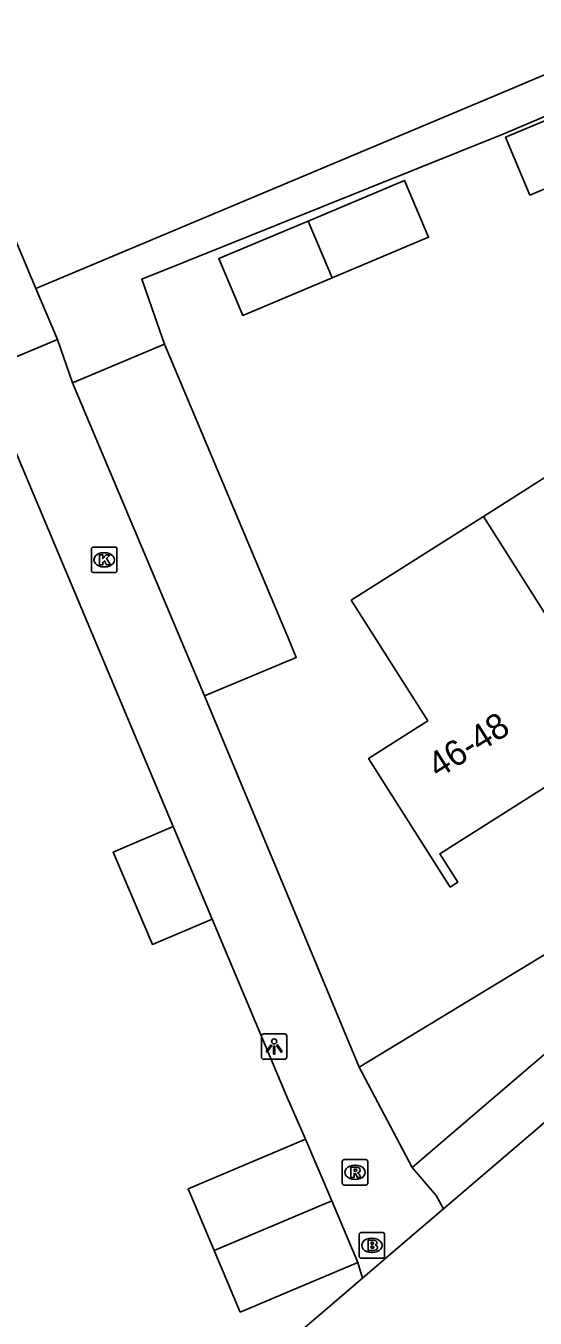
# Model space of a CAD drawing. Extents: x 157767 to 159171, y 387842 to 389425.
# Drawn here: x 158989.6 to 159009.6, y 388129.2 to 388179.9 of the extents above; entities that cross this region are included whole.
import ezdxf

# ---------------------------------------------------------------- set-up
doc = ezdxf.new("R2010")
doc.units = 0
for name, color, linetype in [('IMGEO_Brandkraan', 7, 'Continuous'), ('IMGEO_Fietspad_gesloten', 7, 'Continuous'), ('IMGEO_Kolk', 7, 'Continuous'), ('IMGEO_Lichtpunt', 7, 'Continuous'), ('IMGEO_Pand', 7, 'Continuous'), ('IMGEO_Pand_nummerreeks', 7, 'Continuous'), ('IMGEO_Rioolput', 7, 'Continuous'), ('IMGEO_Voetpad_open', 7, 'Continuous')]:
    doc.layers.add(name, color=color, linetype=linetype)

msp = doc.modelspace()

# ---------------------------------------------------------------- linework, layer by layer
at = {"layer": 'IMGEO_Brandkraan'}
for p, q in [((159002.719, 388131.627), (159002.719, 388132.479)), ((159002.794, 388132.553), (159003.646, 388132.553)), ((159003.207, 388132.333), (159003.232, 388132.333)), ((159003.72, 388132.479), (159003.72, 388131.627)), ((159003.23, 388131.773), (159003.205, 388131.773)), ((159003.646, 388131.553), (159002.794, 388131.553))]:
    msp.add_line(p, q, dxfattribs=at)
for points in [[(159002.719, 388131.627), (159002.719, 388132.479)], [(159002.794, 388132.553), (159003.646, 388132.553)], [(159003.72, 388132.479), (159003.72, 388131.627)], [(159003.067, 388132.253), (159003.067, 388131.853), (159003.28, 388131.853)], [(159003.298, 388132.253), (159003.067, 388132.253)], [(159003.246, 388132.172), (159003.192, 388132.172), (159003.192, 388132.096)], [(159003.192, 388132.096), (159003.245, 388132.096)], [(159003.254, 388132.02), (159003.192, 388132.02), (159003.192, 388131.939)], [(159003.192, 388131.939), (159003.254, 388131.939)], [(159003.646, 388131.553), (159002.794, 388131.553)]]:
    msp.add_lwpolyline(points, dxfattribs=at)
for centre, radius, start, end in [((159002.796, 388132.477), 0.0765, 91.552, 178.448), ((159002.796, 388132.477), 0.0765, 91.552, 178.448), ((159003.644, 388132.477), 0.0765, 1.552, 88.448), ((159003.644, 388132.477), 0.0765, 1.552, 88.448), ((159003.247, 388132.134), 0.0379, 267.8285, 90.9355), ((159003.255, 388131.979), 0.0404, 269.8759, 90.5077), ((159003.286, 388132.104), 0.251, 268.6676, 293.5347), ((159003.302, 388132.108), 0.145, 59.4692, 91.5367), ((159003.327, 388132.155), 0.0922, 285.5137, 58.1501), ((159003.332, 388131.963), 0.105, 301.3115, 78.989), ((159002.796, 388131.629), 0.0765, 181.552, 268.448), ((159002.796, 388131.629), 0.0765, 181.552, 268.448), ((159003.644, 388131.629), 0.0765, 271.552, 358.448), ((159003.644, 388131.629), 0.0765, 271.552, 358.448)]:
    msp.add_arc(centre, radius, start, end, dxfattribs=at)
for centre, major_axis, ratio, start_param, end_param in [((159003.206, 388132.053), (-0.387, 0.002), 0.722429, 4.712389, 7.853982), ((159003.231, 388132.053), (-0.39, 0.002), 0.717154, 1.570796, 4.712389)]:
    msp.add_ellipse(centre, major_axis=major_axis, ratio=ratio, start_param=start_param, end_param=end_param, dxfattribs=at)
at = {"layer": 'IMGEO_Fietspad_gesloten'}
for points in [[(159053.249, 388168.568), (159030.332, 388154.206), (159025.936, 388150.51), (159006.031, 388133.49)], [(159006.031, 388133.49), (159004.522, 388132.2), (159002.853, 388130.771)], [(159002.853, 388130.771), (158986.676, 388116.918), (158982.857, 388113.648)]]:
    msp.add_lwpolyline(points, dxfattribs=at)
at = {"layer": 'IMGEO_Kolk'}
for p, q in [((158992.214, 388158.538), (158992.214, 388159.39)), ((158992.289, 388159.464), (158993.141, 388159.464)), ((158992.702, 388159.244), (158992.727, 388159.244)), ((158993.215, 388159.39), (158993.215, 388158.538)), ((158992.725, 388158.684), (158992.7, 388158.684)), ((158993.141, 388158.464), (158992.289, 388158.464))]:
    msp.add_line(p, q, dxfattribs=at)
for points in [[(158992.214, 388158.538), (158992.214, 388159.39)], [(158992.289, 388159.464), (158993.141, 388159.464)], [(158992.535, 388159.164), (158992.658, 388159.164), (158992.658, 388159.013), (158992.788, 388159.164), (158992.952, 388159.164), (158992.806, 388159.013), (158992.959, 388158.764), (158992.807, 388158.764), (158992.722, 388158.928), (158992.658, 388158.861), (158992.658, 388158.764), (158992.535, 388158.764), (158992.535, 388159.164)], [(158993.215, 388159.39), (158993.215, 388158.538)], [(158993.141, 388158.464), (158992.289, 388158.464)]]:
    msp.add_lwpolyline(points, dxfattribs=at)
for centre, start, end in [((158992.291, 388159.388), 91.552, 178.448), ((158992.291, 388159.388), 91.552, 178.448), ((158993.139, 388159.388), 1.552, 88.448), ((158993.139, 388159.388), 1.552, 88.448), ((158992.291, 388158.54), 181.552, 268.448), ((158992.291, 388158.54), 181.552, 268.448), ((158993.139, 388158.54), 271.552, 358.448), ((158993.139, 388158.54), 271.552, 358.448)]:
    msp.add_arc(centre, 0.0765, start, end, dxfattribs=at)
for centre, major_axis, ratio, start_param, end_param in [((158992.701, 388158.964), (-0.387, 0.002), 0.722429, 4.712389, 7.853982), ((158992.726, 388158.964), (-0.39, 0.002), 0.717154, 1.570796, 4.712389)]:
    msp.add_ellipse(centre, major_axis=major_axis, ratio=ratio, start_param=start_param, end_param=end_param, dxfattribs=at)
at = {"layer": 'IMGEO_Lichtpunt'}
for p, q in [((158998.885, 388140.262), (158998.885, 388139.455)), ((158998.885, 388140.262), (158998.885, 388139.455)), ((158999.787, 388140.357), (158998.979, 388140.357)), ((158999.787, 388140.357), (158998.979, 388140.357)), ((158999.881, 388139.455), (158999.881, 388140.262)), ((158999.881, 388139.455), (158999.881, 388140.262)), ((158998.979, 388139.361), (158999.787, 388139.361)), ((158998.979, 388139.361), (158999.787, 388139.361))]:
    msp.add_line(p, q, dxfattribs=at)
for points in [[(158999.259, 388139.926), (158999.298, 388139.898), (158999.11, 388139.636), (158999.072, 388139.663), (158999.259, 388139.926)], [(158999.471, 388139.898), (158999.509, 388139.925), (158999.696, 388139.663), (158999.657, 388139.635), (158999.471, 388139.898)], [(158999.361, 388139.878), (158999.408, 388139.878), (158999.408, 388139.556), (158999.361, 388139.556), (158999.361, 388139.878)]]:
    msp.add_lwpolyline(points, dxfattribs=at)
msp.add_circle((158999.384, 388140.06), 0.0994, dxfattribs=at)
for centre, start, end in [((158998.979, 388140.262), 90, 180), ((158998.979, 388140.262), 90, 180), ((158999.787, 388140.262), 0, 90), ((158999.787, 388140.262), 0, 90), ((158998.979, 388139.455), 180, 270), ((158998.979, 388139.455), 180, 270), ((158999.787, 388139.455), 270, 0), ((158999.787, 388139.455), 270, 360)]:
    msp.add_arc(centre, 0.0946, start, end, dxfattribs=at)
at = {"layer": 'IMGEO_Pand'}
for points in [[(159012.093, 388177.078), (159008.463, 388175.549), (159009.418, 388173.282), (159013.048, 388174.811)], [(159001.655, 388170.032), (159005.444, 388171.628), (159004.504, 388173.858), (159000.716, 388172.262)], [(159000.716, 388172.262), (159000.341, 388172.105), (158997.211, 388170.786), (158998.151, 388168.556), (159001.655, 388170.032)], [(159001.655, 388170.032), (159000.716, 388172.262)], [(158987.408, 388170.892), (158989.185, 388171.639), (158990.035, 388169.616)], [(158990.035, 388169.616), (158990.878, 388167.608)], [(158990.878, 388167.608), (158989.104, 388166.863)], [(158991.474, 388165.913), (158995.076, 388167.43)], [(158995.076, 388167.43), (159000, 388155.739), (159000.254, 388155.135), (159000, 388155.028), (158996.653, 388153.618)], [(158996.653, 388153.618), (158991.474, 388165.913)], [(159007.593, 388160.666), (159012.68, 388163.891)], [(159013.094, 388151.989), (159005.882, 388147.416), (159006.587, 388146.305), (159006.293, 388146.118), (159003.092, 388151.167), (159005.411, 388152.637), (159002.406, 388157.377), (159007.593, 388160.666)], [(159007.593, 388160.666), (159013.094, 388151.989)], [(158996.953, 388144.862), (158994.605, 388143.866), (158993.067, 388147.494), (158995.415, 388148.489)], [(158995.415, 388148.489), (158996.953, 388144.862)], [(158997.033, 388131.851), (158996.011, 388134.27), (159000, 388135.956), (159000.62, 388136.217)], [(159000.62, 388136.217), (159001.644, 388133.794)], [(159001.644, 388133.794), (158997.033, 388131.851)], [(159001.644, 388133.794), (159002.664, 388131.38)], [(159002.664, 388131.38), (159000, 388130.255), (158998.055, 388129.433), (158997.033, 388131.851)]]:
    msp.add_lwpolyline(points, dxfattribs=at)
at = {"layer": 'IMGEO_Rioolput'}
for p, q in [((159002.058, 388134.495), (159002.058, 388135.347)), ((159002.133, 388135.421), (159002.985, 388135.421)), ((159003.059, 388135.347), (159003.059, 388134.495)), ((159002.546, 388135.201), (159002.571, 388135.201)), ((159002.985, 388134.421), (159002.133, 388134.421)), ((159002.569, 388134.641), (159002.544, 388134.641))]:
    msp.add_line(p, q, dxfattribs=at)
for points in [[(159002.058, 388134.495), (159002.058, 388135.347)], [(159002.133, 388135.421), (159002.985, 388135.421)], [(159003.059, 388135.347), (159003.059, 388134.495)], [(159002.647, 388135.119), (159002.395, 388135.121), (159002.395, 388134.721)], [(159002.395, 388134.721), (159002.519, 388134.721), (159002.519, 388134.883), (159002.53, 388134.883)], [(159002.573, 388135.04), (159002.519, 388135.04), (159002.519, 388134.959)], [(159002.519, 388134.959), (159002.571, 388134.959)], [(159002.577, 388134.854), (159002.648, 388134.721), (159002.788, 388134.721), (159002.723, 388134.847)], [(159002.985, 388134.421), (159002.133, 388134.421)]]:
    msp.add_lwpolyline(points, dxfattribs=at)
for centre, radius, start, end in [((159002.135, 388135.345), 0.0765, 91.552, 178.448), ((159002.135, 388135.345), 0.0765, 91.552, 178.448), ((159002.983, 388135.345), 0.0765, 1.552, 88.448), ((159002.983, 388135.345), 0.0765, 1.552, 88.448), ((159002.529, 388134.83), 0.0533, 26.0293, 88.6989), ((159002.555, 388135.148), 0.19, 274.7715, 282.9687), ((159002.579, 388134.944), 0.0964, 77.0061, 93.1865), ((159002.593, 388135.001), 0.0378, 276.6634, 79.6772), ((159002.646, 388135.009), 0.109, 350.3612, 89.416), ((159002.644, 388135.009), 0.112, 277.5842, 350.9817), ((159002.628, 388134.794), 0.108, 29.5134, 73.7905), ((159002.135, 388134.497), 0.0765, 181.552, 268.448), ((159002.135, 388134.497), 0.0765, 181.552, 268.448), ((159002.983, 388134.497), 0.0765, 271.552, 358.448), ((159002.983, 388134.497), 0.0765, 271.552, 358.448)]:
    msp.add_arc(centre, radius, start, end, dxfattribs=at)
for centre, major_axis, ratio, start_param, end_param in [((159002.545, 388134.921), (-0.387, 0.002), 0.722429, 4.712389, 7.853982), ((159002.57, 388134.921), (-0.39, 0.002), 0.717154, 1.570796, 4.712389)]:
    msp.add_ellipse(centre, major_axis=major_axis, ratio=ratio, start_param=start_param, end_param=end_param, dxfattribs=at)
at = {"layer": 'IMGEO_Voetpad_open'}
for points in [[(158990.035, 388169.616), (159008.568, 388177.4), (159017.257, 388181.095), (159017.848, 388179.704), (159008.394, 388175.684), (158994.187, 388169.978), (158995.076, 388167.43)], [(159002.726, 388139.044), (159013.325, 388145.486), (159029.981, 388159.793), (159046.036, 388170.11)], [(158991.474, 388165.913), (158990.878, 388167.608)], [(158995.415, 388148.489), (158989.11, 388163.499), (158960.785, 388151.731)], [(158996.653, 388153.618), (159000, 388145.586), (159002.726, 388139.044)], [(159004.797, 388135.109), (159026.872, 388154.005)], [(159000.62, 388136.217), (159000, 388137.619), (158999.939, 388137.764), (158996.953, 388144.862)], [(159004.797, 388135.109), (159002.726, 388139.044)], [(159006.031, 388133.49), (159005.743, 388134.008), (159004.797, 388135.109)], [(159002.853, 388130.771), (159002.664, 388131.38)]]:
    msp.add_lwpolyline(points, dxfattribs=at)

# ---------------------------------------------------------------- texts
at = {"layer": 'IMGEO_Pand_nummerreeks'}
msp.add_text('46-48', height=1, rotation=32.3781, dxfattribs=at).set_placement((159005.822, 388150.362))

doc.saveas('drawing.dxf')
